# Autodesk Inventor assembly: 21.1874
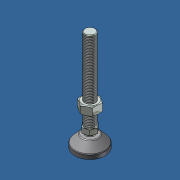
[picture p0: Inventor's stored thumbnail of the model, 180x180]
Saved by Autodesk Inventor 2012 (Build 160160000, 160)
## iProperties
Created: 2007-03
Part Number: 21.1874
Document SubType Name: Assembly
Designer: Andy Moles
Mass: 322.821 g
Surface Area: 199.95 cm^2
Volume: 60.2098 cm^3
Density: 5.3616 g/cm^3
Description: LEVELING FOOT M16 45mm BASE
Author: Andy Moles
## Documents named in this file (5)
- C:\Andys Backup Data\ANDY'S INVENTOR\INVENTOR LIBRARIES\PARTS LIBRARY\FEET WHEELS FLOOR FASTENING SUPPORTS\21.1874 LEVELING FOOT M16 45mm BASE.iam
- C:\Andys Backup Data\ANDY'S INVENTOR\INVENTOR LIBRARIES\PARTS LIBRARY\FEET WHEELS FLOOR FASTENING SUPPORTS\SUBCOMPONENTS\LEVELING FEET SUBCOMPONENTS\PAD 45mm PLASTIC.ipt
- C:\Andys Backup Data\ANDY'S INVENTOR\INVENTOR LIBRARIES\PARTS LIBRARY\FEET WHEELS FLOOR FASTENING SUPPORTS\SUBCOMPONENTS\LEVELING FEET SUBCOMPONENTS\ANTI-SKID PAD 45mm.ipt
- C:\Andys Backup Data\ANDY'S INVENTOR\INVENTOR LIBRARIES\PARTS LIBRARY\FASTENING ELEMENTS\NUTS\21.1529 M16 HEX NUT.ipt
- C:\Andys Backup Data\ANDY'S INVENTOR\INVENTOR LIBRARIES\PARTS LIBRARY\FEET WHEELS FLOOR FASTENING SUPPORTS\SUBCOMPONENTS\LEVELING FEET SUBCOMPONENTS\THREADED STUD 16mm SHORTER.ipt
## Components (4 placed, 4 different names)
1. ANTI-SKID PAD 45mm:1 — Insert:1
2. PAD 45mm PLASTIC:1 — Insert:1, Tangent:1, Mate:1
3. THREADED STUD 16mm SHORTER:1 — Tangent:1, Mate:1, Mate:2
4. 21.1529 M16 HEX NUT:1 — Mate:2
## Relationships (4: Mate 2, Insert 1, Tangent 1)
- Insert:1: ANTI-SKID PAD 45mm:1 ↔ PAD 45mm PLASTIC:1
- Tangent:1: PAD 45mm PLASTIC:1 ↔ THREADED STUD 16mm SHORTER:1
- Mate:1: PAD 45mm PLASTIC:1 ↔ THREADED STUD 16mm SHORTER:1
- Mate:2: THREADED STUD 16mm SHORTER:1 ↔ 21.1529 M16 HEX NUT:1
